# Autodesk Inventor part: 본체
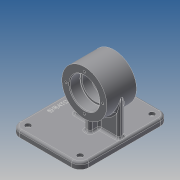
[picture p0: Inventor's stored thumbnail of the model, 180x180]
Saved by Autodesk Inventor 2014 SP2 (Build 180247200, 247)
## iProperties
Created: 2019-09
Part Number: 본체
Material: Generic
Document SubType Name: Modeling
Designer: kb542-10
Density: 1 g/cm^3
Appearance: Default
Author: kb542-10
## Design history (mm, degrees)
sketch "스케치1"
  geometry: C1 r 32 at (0, 0); 1 further point
  constraints: 1 centre point, 1 coincident
  dimensions: "d0" = 64 diameter of C1
extrude "돌출1" new body sketch "스케치1" stored distance "d1" = 42; taper "d2" = 0 deg
sketch "스케치2"
  geometry: C1 r 32 at (0, 0) reference; C2 r 21 at (0, 0)
  constraints: 1 centre point, 1 coincident
  dimensions: "d3" = 42 diameter of C2
extrude "돌출2" cut sketch "스케치2" distance "d4" = 15; taper "d5" = 0 deg
sketch "스케치3"
  geometry: C1 r 32 at (0, 0) reference; C2 r 21 at (0, 0)
  constraints: 1 centre point, 1 coincident
  dimensions: "d6" = 42 diameter of C2
extrude "돌출3" cut sketch "스케치3" distance "d7" = 15; taper "d8" = 0 deg
sketch "스케치4"
  geometry: C1 r 21 at (0, 0) reference; C2 r 18 at (0, 0)
  constraints: 1 centre point, 1 coincident
  dimensions: "d9" = 36 diameter of C2
extrude "돌출4" cut sketch "스케치4" stored distance "d10" = 15; taper "d11" = 0 deg
sketch "스케치7"
  geometry: L1 (-63, -50)-(63, -50); L2 (63, -50)-(63, -59); L3 (63, -59)-(-63, -59); L4 (-63, -59)-(-63, -50); L5 (-21, -32)-(21, -32) reference; 2 further points
  constraints: 8 end point, 2 parallel, 1 horizontal, 1 midpoint, 1 perpendicular, 1 vertical alignment
  dimensions: "d15" = 59 distance from line of L3 point (0, 0); "d16" = 9 distance of L1.end L2.end; "d17" = 126 distance of L1.start L1.end
extrude "돌출5" join sketch "스케치7" distance "d18" = 36; taper "d20" = 0 deg; dims "d19" = 62, "d21" = 0
sketch "스케치8"
  geometry: L1 (-36, -50)-(62, -50) reference; L2 (-36, -59)-(-36, -50) reference; L3 (-36, -59)-(62, -59) reference; L4 (62, -50)-(62, -59) reference; L5 (32, 0)-(32, -50); L6 (-32, 0)-(-32, -50); A1 r 32 centre (0, 0) between (32, 0) and (-32, 0) reference; 1 further point
  constraints: 4 end point, 2 perpendicular, 2 point on circle, 2 point on line, 2 tangent
extrude "돌출6" join sketch "스케치8" stored distance "d22" = 8; taper "d23" = 0 deg
sketch "스케치9"
  geometry: L1 (-21, -32)-(21, -32) reference; L2 (63, -50)-(-63, -50) reference; L3 (-17, -32)-(-17, -50); L4 (17, -32)-(17, -50); 1 further point
  constraints: 4 end point, 4 point on line, 2 perpendicular
  dimensions: "d24" = 17 distance from line of L4 point (0, 0); "d25" = 17 distance from line of L3 point (0, 0)
feature "리브1" dims "d53" = 1, "d54" = 8, "d55" = 0, "d56" = 0, "d57" = 1, "d58" = 1
feature "리브2" dims "d59" = 1, "d60" = 8, "d61" = 0, "d62" = 0, "d63" = 1, "d64" = 1
sketch "스케치10"
  geometry: C1 r 21 at (0, 0) reference; 1 further point
  constraints: 1 vertical alignment
  dimensions: "d28" = 26 distance of C1.centre point (0, 26)
hole "구멍1" sketch "스케치10" at (0, 26) diameter "d29" = 3.242; stored, may be unused: countersink angle "d33" = 90 deg, drill point angle "d35" = 118 deg; dims "d30" = 8, "d31" = 4, "d32" = 2, "d34" = 10
fillet "모깎기1" dims "d39" = 12
sketch "스케치11"
  geometry: A1 r 12 centre (74, -12) between (86, -12) and (74, 0) reference; A2 r 12 centre (0, -12) between (0, 0) and (-12, -12) reference; A3 r 12 centre (0, -114) between (-12, -114) and (0, -126) reference; A4 r 12 centre (74, -114) between (74, -126) and (86, -114) reference; 5 further points
  constraints: 4 coincident
hole "구멍2" sketch "스케치11" at (0, -12), (0, -114), (74, -114), (74, -12) diameter "d40" = 3.242; stored, may be unused: countersink angle "d44" = 90 deg, drill point angle "d46" = 118 deg; dims "d41" = 4.5, "d42" = 8, "d43" = 4.4, "d45" = 10
fillet "모깎기2" dims "d51" = 3
fillet "모깎기4" dims "d65" = 3
fillet "모깎기5" dims "d66" = 3
fillet "모깎기6" dims "d67" = 3
fillet "모깎기7" dims "d68" = 0.3
chamfer "모따기1" distance "d69" = 1; stored, may be unused: second distance "d70" = 2, angle "d71" = 45 deg
sketch "스케치13"
  geometry: L1 (74, 3)-(0, 3) reference; L2 (-12, -9)-(-12, -111) reference; 2 further points
  constraints: 1 other
  dimensions: "d72" = 63 distance from line of point (-2, -60) L1; "d73" = 10 distance from line of point (-2, -60) L2
feature "엠보싱2" sketch "스케치13" dims "d1" = 42, "d2" = 0, "d74" = 0.5, "d75" = 0
node "솔리드1"
pattern_circular "원형 패턴1" dims angle "d37" = 360 deg
mirror "대칭1"
node "투영된 루프1"
